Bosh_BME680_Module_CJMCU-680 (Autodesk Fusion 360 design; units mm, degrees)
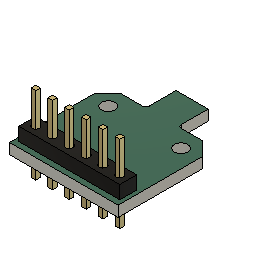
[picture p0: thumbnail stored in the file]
sketch "スケッチ" plane through (0, -1, 0) normal (0, -1, 0) x axis (1, 0, 0)
  line L1 (7.5, 10) -> (7.5, 0)
  line L2 (0, 10) -> (7.5, 10)
  line L3 (6.29, 1.19) -> (6.29, 2.46)
  curve K1
  curve K2
  curve K3
  curve K4
  line L4 (12.54, 10) -> (10, 10)
  line L5 (12.54, 7.9) -> (12.54, 10)
  line L6 (10, 7.9) -> (12.54, 7.9)
  line L7 (10, 10) -> (10, 7.9)
  line L8 (15.08, 10) -> (12.54, 10)
  line L9 (15.08, 7.9) -> (15.08, 10)
  line L10 (12.54, 7.9) -> (15.08, 7.9)
  line L11 (12.54, 10) -> (12.54, 7.9)
  line L12 (20.16, 10) -> (17.62, 10)
  line L13 (20.16, 7.9) -> (20.16, 10)
  line L14 (17.62, 7.9) -> (20.16, 7.9)
  line L15 (17.62, 10) -> (17.62, 7.9)
  line L16 (17.62, 7.9) -> (17.62, 10)
  line L17 (15.08, 10) -> (15.08, 7.9)
  line L18 (17.62, 10) -> (15.08, 10)
  line L19 (15.08, 7.9) -> (17.62, 7.9)
  line L20 (22.7, 7.9) -> (22.7, 10)
  line L21 (20.16, 7.9) -> (22.7, 7.9)
  line L22 (20.16, 10) -> (20.16, 7.9)
  line L23 (22.7, 10) -> (20.16, 10)
  line L24 (25.24, 10) -> (22.7, 10)
  line L25 (25.24, 7.9) -> (25.24, 10)
  line L26 (22.7, 10) -> (22.7, 7.9)
  line L27 (22.7, 7.9) -> (25.24, 7.9)
  line L28 (21.815, 10) -> (10, 10)
  line L29 (21.815, -4.8) -> (21.815, 10)
  line L30 (10, 10) -> (10, -4.8)
  line L31 (10.691, 10) -> (10, 10)
  line L32 (10.691, -2.8) -> (10.691, 10)
  line L33 (10, -2.8) -> (10.691, -2.8)
  line L34 (10, 10) -> (10, -2.8)
  line L35 (12.691, -4.8) -> (10.691, -2.8)
  line L36 (13.5194, -2.8) -> (10.691, -2.8)
  line L37 (18.89, 10) -> (17.62, 10)
  line L38 (18.89, 7.9) -> (18.89, 10)
  line L39 (17.62, 7.9) -> (18.89, 7.9)
  line L40 (17.62, 10) -> (17.62, 7.9)
  line L41 (25.089, -4.8) -> (27.089, -2.8)
  line L42 (27.089, -2.8) -> (27.089, 10)
  line L43 (21.815, -4.8) -> (25.089, -4.8)
  line L44 (15.965, -4.8) -> (12.691, -4.8)
  line L45 (21.315, 10) -> (10, 10)
  line L46 (21.315, -5.3) -> (21.315, 10)
  line L47 (10, -5.3) -> (21.315, -5.3)
  line L48 (10, 10) -> (10, -5.3)
  line L49 (16.465, 10) -> (10, 10)
  line L50 (16.465, -5.3) -> (16.465, 10)
  line L51 (10, -5.3) -> (16.465, -5.3)
  line L52 (10, 10) -> (10, -5.3)
  line L53 (21.315, 10) -> (10, 10)
  line L54 (21.315, -9.37) -> (21.315, 10)
  line L55 (10, -9.37) -> (21.315, -9.37)
  line L56 (10, 10) -> (10, -9.37)
  line L57 (16.465, 10) -> (10, 10)
  line L58 (16.465, -9.37) -> (16.465, 10)
  line L59 (10, -9.37) -> (16.465, -9.37)
  line L60 (10, 10) -> (10, -9.37)
  line L61 (16.465, -9.37) -> (16.465, -5.3)
  line L62 (21.315, -9.37) -> (16.465, -9.37)
  line L63 (21.315, -5.3) -> (21.315, -9.37)
  line L64 (16.465, -4.8) -> (15.965, -4.8)
  line L65 (16.465, -5.3) -> (16.465, -4.8)
  line L66 (15.965, -5.3) -> (16.465, -5.3)
  line L67 (15.965, -4.8) -> (15.965, -5.3)
  line L68 (21.315, -4.8) -> (21.815, -4.8)
  line L69 (21.315, -5.3) -> (21.315, -4.8)
  line L70 (21.815, -5.3) -> (21.315, -5.3)
  line L71 (21.815, -4.8) -> (21.815, -5.3)
  line L72 (12.19, 7.9) -> (12.54, 7.9)
  line L73 (12.19, 7.55) -> (12.19, 7.9)
  line L74 (12.54, 7.55) -> (12.19, 7.55)
  line L75 (12.54, 7.9) -> (12.54, 7.55)
  line L76 (12.89, 7.55) -> (12.19, 7.55)
  line L77 (12.89, 8.25) -> (12.89, 7.55)
  line L78 (12.19, 8.25) -> (12.89, 8.25)
  line L79 (12.19, 7.55) -> (12.19, 8.25)
  line L80 (15.43, 7.55) -> (14.73, 7.55)
  line L81 (15.43, 8.25) -> (15.43, 7.55)
  line L82 (14.73, 8.25) -> (15.43, 8.25)
  line L83 (14.73, 7.55) -> (14.73, 8.25)
  line L84 (17.97, 7.55) -> (17.27, 7.55)
  line L85 (17.97, 8.25) -> (17.97, 7.55)
  line L86 (17.27, 8.25) -> (17.97, 8.25)
  line L87 (17.27, 7.55) -> (17.27, 8.25)
  line L88 (20.51, 7.55) -> (19.81, 7.55)
  line L89 (20.51, 8.25) -> (20.51, 7.55)
  line L90 (19.81, 7.55) -> (19.81, 8.25)
  line L91 (19.81, 8.25) -> (20.51, 8.25)
  line L92 (23.05, 7.55) -> (22.35, 7.55)
  line L93 (23.05, 8.25) -> (23.05, 7.55)
  line L94 (22.35, 8.25) -> (23.05, 8.25)
  line L95 (22.35, 7.55) -> (22.35, 8.25)
  line L96 (25.59, 7.55) -> (24.89, 7.55)
  line L97 (25.59, 8.25) -> (25.59, 7.55)
  line L98 (24.89, 7.55) -> (24.89, 8.25)
  line L99 (24.89, 8.25) -> (25.59, 8.25)
  line L100 (27.089, 10) -> (10, 10)
  line L101 (16.465, 10) -> (18.89, 10)
  line L102 (16.465, -9.37) -> (16.465, 10)
  line L103 (18.89, -9.37) -> (16.465, -9.37)
  line L104 (18.89, 10) -> (18.89, -9.37)
  line L105 (17.39, -5.3) -> (18.89, -5.3)
  line L106 (17.39, -9.37) -> (17.39, -5.3)
  line L107 (18.89, -9.37) -> (17.39, -9.37)
  line L108 (18.89, -5.3) -> (18.89, -9.37)
  line L109 (20.39, -5.3) -> (18.89, -5.3)
  line L110 (20.39, -9.37) -> (20.39, -5.3)
  line L111 (18.89, -9.37) -> (20.39, -9.37)
  line L112 (18.89, -5.3) -> (18.89, -9.37)
  line L113 (20.541, -9.37) -> (17.39, -9.37)
  line L114 (20.541, -8.37) -> (20.541, -9.37)
  line L115 (17.39, -8.37) -> (20.541, -8.37)
  line L116 (17.39, -9.37) -> (17.39, -8.37)
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  point P32 (10.691, 10)
  point P42 (27.089, 10)
  point P33 (10.691, -2.8)
  point P40 (27.089, -2.8)
  point P35 (12.691, -4.8)
  point P41 (25.089, -4.8)
  point P30 (21.815, -4.8)
  point P44 (15.965, -4.8)
  point P43 (12.691, -4.8)
  point P58 (15.965, -5.3)
  point P61 (15.965, -5.3)
  point P60 (21.815, -5.3)
  point P62 (21.815, -5.3)
  point P9 (12.54, 7.9)
  point P64 (12.54, 7.9)
  point P98 (18.89, -5.3)
  point P109 (13.39, -2.2)
  point P111 (13.39, -2.2)
  point P7 (10, 10)
  point P8 (12.54, 10)
  point P10 (10, 7.9)
  point P11 (15.08, 10)
  point P13 (12.54, 7.9)
  point P15 (15.08, 10)
  point P16 (17.62, 10)
  point P19 (15.08, 7.9)
  point P21 (20.16, 10)
  point P17 (17.62, 7.9)
  point P22 (20.16, 10)
  point P23 (22.7, 10)
  point P26 (20.16, 7.9)
  point P28 (25.24, 10)
  point P24 (22.7, 7.9)
  point P29 (21.815, 10)
  point P31 (10, -4.8)
  point P34 (10, -2.8)
  point P37 (18.89, 10)
  point P45 (21.315, 10)
  point P47 (10, -5.3)
  point P48 (16.465, 10)
  point P50 (10, -5.3)
  point P51 (21.315, 10)
  point P53 (10, -9.37)
  point P54 (16.465, 10)
  point P56 (10, -9.37)
  point P65 (12.19, 7.9)
  point P67 (12.54, 7.55)
  point P66 (12.19, 7.55)
  point P68 (12.89, 7.55)
  point P70 (12.19, 8.25)
  point P71 (15.43, 7.55)
  point P74 (14.73, 7.55)
  point P75 (14.73, 8.25)
  point P76 (17.97, 7.55)
  point P79 (17.27, 7.55)
  point P83 (17.27, 8.25)
  point P82 (19.81, 7.55)
  point P84 (20.51, 7.55)
  point P85 (19.81, 8.25)
  point P89 (22.35, 7.55)
  point P91 (23.05, 7.55)
  point P87 (22.35, 8.25)
  point P88 (25.59, 7.55)
  point P93 (24.89, 7.55)
  point P86 (24.89, 8.25)
  point P99 (17.39, -5.3)
  point P102 (20.39, -5.3)
  point P100 (17.39, -9.37)
  point P107 (17.39, -8.37)
  point P108 (13.39, 10)
  point P110 (10, -2.2)
  point P115 (11.27, 7.9)
  point P117 (12.54, 9.17)
  point P25 (25.24, 7.9)
  point P118 (26.51, 7.9)
  point P120 (25.24, 6.63)
  vertical L3
  horizontal L4
  vertical L5
  horizontal L6
  vertical L7
  horizontal L8
  vertical L9
  horizontal L10
  vertical L11
  horizontal L18
  vertical L16
  horizontal L19
  vertical L17
  horizontal L12
  vertical L13
  horizontal L14
  vertical L15
  horizontal L23
  vertical L20
  horizontal L21
  vertical L22
  horizontal L24
  vertical L25
  horizontal L27
  vertical L26
  horizontal L28
  vertical L29
  vertical L30
  horizontal L31
  vertical L32
  horizontal L33
  vertical L34
  horizontal L36
  horizontal L37
  vertical L38
  horizontal L39
  vertical L40
  symmetric P32 L38 P42
  symmetric P33 L38 P40
  symmetric P35 L38 P41
  symmetric P30 L38 P44
  symmetric L38 P41 P43
  horizontal L45
  vertical L46
  horizontal L47
  vertical L48
  horizontal L49
  vertical L50
  horizontal L51
  vertical L52
  horizontal L53
  vertical L54
  horizontal L55
  vertical L56
  horizontal L57
  vertical L58
  horizontal L59
  vertical L60
  horizontal L64
  vertical L65
  horizontal L66
  vertical L67
  horizontal L68
  vertical L69
  horizontal L70
  vertical L71
  coincident P58 P61
  coincident P60 P62
  coincident P9 P64
  horizontal L72
  vertical L73
  horizontal L74
  vertical L75
  horizontal L76
  vertical L77
  horizontal L78
  vertical L79
  horizontal L80
  vertical L81
  horizontal L82
  vertical L83
  horizontal L84
  vertical L85
  horizontal L86
  vertical L87
  horizontal L88
  vertical L89
  horizontal L91
  vertical L90
  horizontal L92
  vertical L93
  horizontal L94
  vertical L95
  horizontal L96
  vertical L97
  horizontal L99
  vertical L98
  horizontal L101
  vertical L102
  horizontal L103
  vertical L104
  horizontal L105
  vertical L106
  horizontal L107
  vertical L108
  coincident L47 P98
  coincident L104 P98
  horizontal L109
  vertical L110
  horizontal L111
  vertical L112
  horizontal L113
  vertical L114
  horizontal L115
  vertical L116
  coincident P109 P111
  dimension "d90" distance P7 P8 = 2.54
  dimension "d91" distance P7 P10 = 2.1
  dimension "d92" distance P8 P11 = 2.54
  dimension "d93" distance P8 P13 = 2.1
  dimension "d94" distance P15 P16 = 2.54
  dimension "d95" distance P15 P19 = 2.1
  dimension "d96" distance P16 P21 = 2.54
  dimension "d97" distance P16 P17 = 2.1
  dimension "d98" distance P22 P23 = 2.54
  dimension "d99" distance P22 P26 = 2.1
  dimension "d100" distance P23 P28 = 2.54
  dimension "d101" distance P23 P24 = 2.1
  dimension "d104" distance P7 P29 = 11.815
  dimension "d105" distance P7 P31 = 14.8
  dimension "d106" distance P7 P32 = 0.691
  dimension "d107" distance P7 P34 = 12.8
  dimension "d108" angle L35 L36 = 45
  dimension "d109" distance P16 P37 = 1.27
  dimension "d110" distance P7 P45 = 11.315
  dimension "d111" distance P7 P47 = 15.3
  dimension "d112" distance P7 P48 = 6.465
  dimension "d113" distance P7 P50 = 15.3
  dimension "d114" distance P7 P51 = 11.315
  dimension "d115" distance P7 P53 = 19.37
  dimension "d116" distance P7 P54 = 6.465
  dimension "d117" distance P7 P56 = 19.37
  dimension "d118" diameter = 1.1
  dimension "d119" distance P9 P65 = 0.35
  dimension "d120" distance P9 P67 = 0.35
  dimension "d121" distance P66 P68 = 0.7
  dimension "d122" distance P66 P70 = 0.7
  dimension "d123" diameter = 1.1
  dimension "d124" distance P71 P74 = 0.7
  dimension "d125" distance P74 P75 = 0.7
  dimension "d126" diameter = 1.1
  dimension "d127" distance P76 P79 = 0.7
  dimension "d128" distance P79 P83 = 0.7
  dimension "d129" diameter = 1.1
  dimension "d130" distance P82 P84 = 0.7
  dimension "d131" distance P82 P85 = 0.7
  dimension "d132" diameter = 1.1
  dimension "d133" distance P89 P91 = 0.7
  dimension "d134" distance P87 P89 = 0.7
  dimension "d135" diameter = 1.1
  dimension "d136" distance P88 P93 = 0.7
  dimension "d137" distance P86 P93 = 0.7
  dimension "d138" distance P98 P99 = 1.5
  dimension "d139" distance P98 P102 = 1.5
  dimension "d140" distance P100 P107 = 1
  dimension "d142" distance P7 P108 = 3.39
  dimension "d143" distance P7 P110 = 12.2
  dimension "d144" diameter = 2
  dimension "d145" diameter = 3
  dimension "d146" distance P9 P115 = 1.27
  dimension "d147" distance P9 P117 = 1.27
  dimension "d148" distance P25 P118 = 1.27
  dimension "d149" distance P25 P120 = 1.27
  dimension "d66" Text3-Height = 1
  dimension "d162" Text2-Height = 0.8
extrude "押し出し16" new body sketch "スケッチ" against normal blind 3.6 bodies "PinHederBase"
extrude "押し出し17" cut of existing geometry blind -1.6
extrude "押し出し18" new body sketch "スケッチ" against normal blind 1.6 bodies "PCB"
extrude "押し出し19" new body sketch "スケッチ" against normal blind 8.6 (magnitude of "-5 mm - 2 mm - 1.6 mm") bodies "Pin3", "Pin6", "Pin2", "Pin4", "Pin5", "Pin1"
extrude "押し出し20" add of existing geometry blind 3.1 (= "11.7 mm - 5 mm - 2 mm - 1.6 mm")
extrude "押し出し21" new body sketch "スケッチ" profile of L47 L104 L105 L106 L108 L109 L110 L112 L115 along normal blind 0.93 bodies "BME680"
extrude "押し出し22" cut sketch "スケッチ" against normal blind 0.1
extrude "押し出し23" new body of existing geometry blind 0.1 bodies "CS-C", "SDO-D", "SDA-A", "SDA-S", "SCL-C", "GND-D", "GND-G", "VCC-C"
named bodies: "PinHederBase", "PCB", "Pin3", "Pin6", "Pin2", "Pin4", "Pin5", "Pin1", "CS-C", "SDO-D", "SDA-A", "SDA-S", "SCL-C", "GND-D", "GND-G", "VCC-C", "CJMCU680-0", "CJMCU680-6", "CJMCU680-U", "CJMCU680-C1", "CJMCU680-J", "CJMCU680-M", "CJMCU680-C", "CJMCU680-8", "VCC-V", "VCC-C2", "GND-N", "SCL-S", "SCL-L", "SDA-D", "SDO-S", "SDO-O", "CS-S", "BME680"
